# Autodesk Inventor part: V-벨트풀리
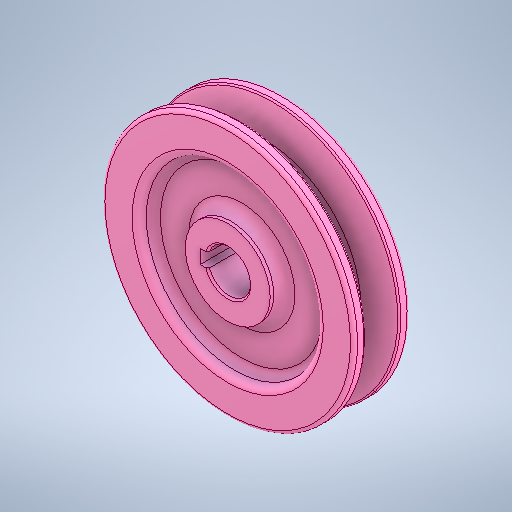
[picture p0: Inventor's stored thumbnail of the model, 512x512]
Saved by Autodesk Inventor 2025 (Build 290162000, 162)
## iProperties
Created: 2024-08
Part Number: V-벨트풀리
Material: 강철, 연강
Document SubType Name: Modeling
Designer: onair
Density: 7.86 g/cm^3
Appearance: 기본값
Author: jhkim
Sending System: Autodesk Inventor 2025
Preprocessor: ST-DEVELOPER v20
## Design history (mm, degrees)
feature "Solid1"
node "솔리드1"
